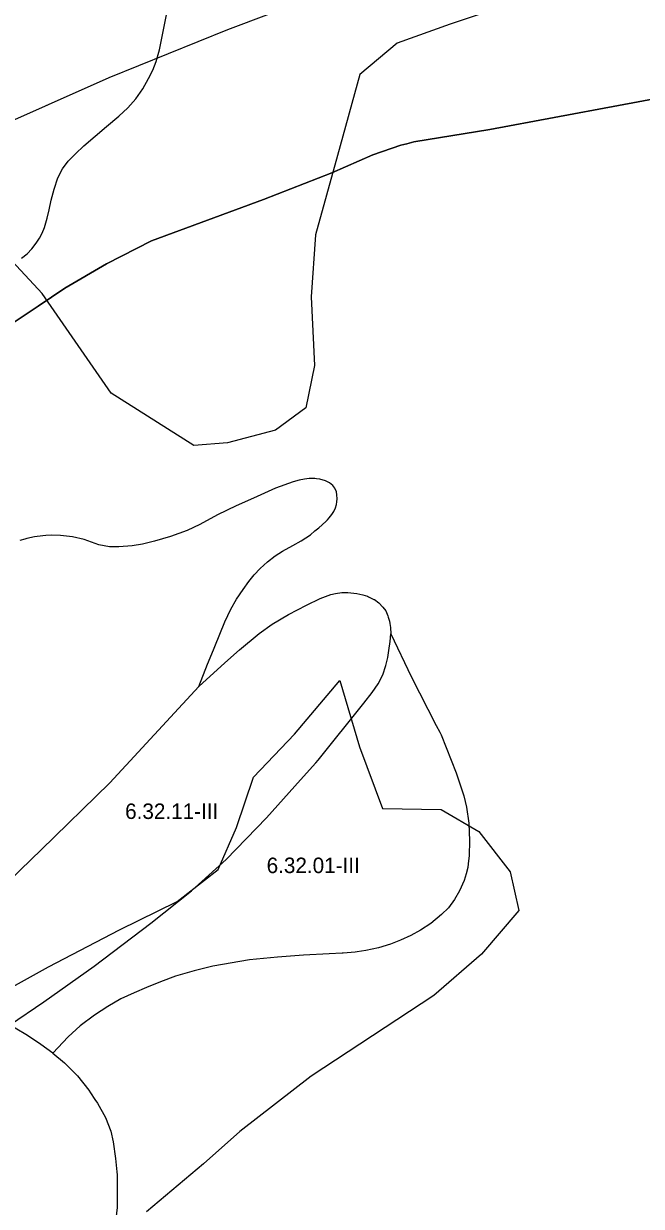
# Model space of a CAD drawing. Extents: x -555156 to -540209, y -1046851 to -1035695.
# Drawn here: x -542146 to -541747, y -1038196 to -1037432 of the extents above; entities that cross this region are included whole.
import ezdxf

# ---------------------------------------------------------------- set-up
doc = ezdxf.new("R2010")
doc.units = 0
for name, color, linetype in [('Vrstva 27', 7, 'Continuous'), ('Vrstva 28', 7, 'Continuous'), ('Vrstva 29', 7, 'Continuous')]:
    doc.layers.add(name, color=color, linetype=linetype)

msp = doc.modelspace()

# ---------------------------------------------------------------- linework, layer by layer
at = {"layer": 'Vrstva 28'}
for points in [[(-542147.76, -1037583.51), (-542144.18, -1037580.64), (-542141.08, -1037577.62), (-542138.22, -1037573.88), (-542136.15, -1037570.69), (-542134.32, -1037567.43), (-542132.8, -1037563.69), (-542131.05, -1037557.64), (-542129.78, -1037552.25), (-542128.66, -1037545.98), (-542126.57, -1037539.01), (-542124.21, -1037531.63), (-542121.14, -1037525.78), (-542117.52, -1037520.76), (-542112.93, -1037516.16), (-542107.36, -1037511.01), (-542092.86, -1037498.54), (-542084.78, -1037491.71), (-542078.93, -1037486.42), (-542073.78, -1037480.57), (-542069.32, -1037474.16), (-542065.7, -1037467.47), (-542062.92, -1037462.04), (-542060.69, -1037456.47), (-542058.53, -1037448.91), (-542049.27, -1037402.1)], [(-541720.19, -1037477.06), (-541844.94, -1037500.38), (-541894.08, -1037508.4), (-541898.72, -1037509.58), (-541902.61, -1037510.57), (-541920.68, -1037516.81), (-541947.21, -1037528.47), (-541991.27, -1037545.59), (-542063.6, -1037572.3), (-542092.72, -1037587.26), (-542119.74, -1037602.87), (-542137.04, -1037614.48), (-542160.81, -1037630.43), (-542163.69, -1037632.79), (-542194.71, -1037658.28), (-542217.42, -1037678.3), (-542231.55, -1037691.99)], [(-542229.29, -1037689.8), (-542217.42, -1037678.3), (-542194.71, -1037658.28), (-542163.69, -1037632.79), (-542160.81, -1037630.43), (-542137.04, -1037614.48), (-542119.74, -1037602.87), (-542092.72, -1037587.26), (-542063.6, -1037572.3), (-541991.27, -1037545.59), (-541947.21, -1037528.47), (-541920.68, -1037516.81), (-541902.61, -1037510.57), (-541898.72, -1037509.58), (-541894.08, -1037508.4), (-541844.94, -1037500.38), (-541720.19, -1037477.06)], [(-541972.41, -1037769.17), (-541966.87, -1037766.27), (-541960.98, -1037762.25), (-541958.08, -1037759.82), (-541955.6, -1037757.73), (-541951.09, -1037753.61), (-541950.04, -1037752.6), (-541948.8, -1037751.41), (-541947.04, -1037749.12), (-541945.77, -1037747.21), (-541944.75, -1037744.92), (-541944.17, -1037742.82), (-541943.87, -1037740.92), (-541943.73, -1037739.06), (-541943.82, -1037736.48), (-541944.17, -1037734.53), (-541945.29, -1037732.09), (-541946.46, -1037730.43), (-541948.65, -1037728.67), (-541951.29, -1037727.35), (-541954.99, -1037726.38), (-541956.94, -1037726.16), (-541958.07, -1037726.03), (-541961.77, -1037726.03), (-541964.85, -1037726.33), (-541968.16, -1037726.91), (-541972.17, -1037728.08), (-541983.52, -1037732.12), (-541997.86, -1037738.54), (-542008.91, -1037743.62), (-542021.01, -1037749.45), (-542032.36, -1037755.58), (-542040.73, -1037759.46), (-542051.48, -1037763.35), (-542061.79, -1037766.49), (-542069.56, -1037768.28), (-542076.13, -1037769.33), (-542084.79, -1037770.08), (-542090.92, -1037770.08), (-542097.64, -1037768.73), (-542107.17, -1037765.31), (-542114.76, -1037763.6), (-542122.45, -1037762.66), (-542128.25, -1037762.58), (-542131.97, -1037762.86), (-542134.05, -1037763.01), (-542139.26, -1037763.69), (-542144.38, -1037764.71), (-542145.51, -1037765.06), (-542148.82, -1037766.08)], [(-542033.02, -1037860.31), (-542027.49, -1037845.96), (-542023.61, -1037836.55), (-542022.74, -1037834.42), (-542016.29, -1037818.62), (-542012.41, -1037810.4), (-542008.67, -1037803.82), (-542004.51, -1037797.61), (-542000.75, -1037792.48), (-541997.34, -1037788.21), (-541993.41, -1037784.03), (-541988.63, -1037779.76), (-541983.85, -1037775.92), (-541978.99, -1037772.93), (-541972.41, -1037769.17)], [(-542033.02, -1037860.31), (-542016.27, -1037845.08), (-542006.71, -1037836.56), (-541994.02, -1037826.1), (-541985.65, -1037820.12), (-541975.2, -1037813.84), (-541963.55, -1037807.71), (-541954.73, -1037803.38), (-541947.86, -1037800.84), (-541944.66, -1037800.18), (-541940.65, -1037799.67), (-541936.89, -1037799.67), (-541931, -1037800.18), (-541927.16, -1037801.03), (-541924.01, -1037802.06), (-541923.4, -1037802.35), (-541919.91, -1037804.02), (-541919.65, -1037804.2), (-541916.67, -1037806.33), (-541914.1, -1037809.06), (-541912.31, -1037811.54), (-541910.95, -1037814.61), (-541910.65, -1037815.56), (-541909.84, -1037818.11), (-541909.61, -1037819.66), (-541909.24, -1037822.13), (-541909.07, -1037826.31)], [(-541909.07, -1037826.31), (-541895.83, -1037853.87), (-541879.6, -1037885.47), (-541877.39, -1037889.78), (-541876.49, -1037891.53), (-541866.82, -1037916.11), (-541861.81, -1037931.05), (-541860.02, -1037938.22), (-541858.53, -1037948.68), (-541858.08, -1037960.04), (-541858.38, -1037969.61), (-541858.9, -1037974.99), (-541859.12, -1037977.23), (-541860.32, -1037981.45), (-541861.51, -1037985.6), (-541864.5, -1037992.32), (-541867.79, -1037998), (-541871.82, -1038003.38), (-541876.15, -1038007.72), (-541883.17, -1038013.55), (-541889.89, -1038017.88), (-541896.17, -1038021.32), (-541902.74, -1038024.31), (-541909.16, -1038026.85), (-541916.93, -1038029.24), (-541925.14, -1038031.03), (-541930.85, -1038031.9), (-541932.01, -1038032.08), (-541939.75, -1038032.62), (-541940.53, -1038032.68), (-541948.82, -1038032.98), (-541965.55, -1038034.03), (-541982.28, -1038035.34), (-542000.31, -1038036.91), (-542024.1, -1038041.09), (-542036.12, -1038044.15), (-542048.21, -1038047.58), (-542057.92, -1038051.17), (-542066.89, -1038054.76), (-542074.8, -1038058.34), (-542083.47, -1038062.23), (-542091.83, -1038067.16), (-542100.49, -1038072.69), (-542109.9, -1038079.57), (-542117.67, -1038086.74)], [(-542100.81, -1038041), (-542064.21, -1038013.28), (-542037.81, -1037992.36), (-542015.33, -1037972.22), (-541989.26, -1037945.15), (-541967.29, -1037920.64), (-541957.37, -1037909.58), (-541956.03, -1037907.91), (-541926.48, -1037871.04), (-541921.1, -1037864.29), (-541917.18, -1037858.66), (-541914.19, -1037852.76), (-541912.14, -1037846.78), (-541910.95, -1037841.49), (-541910.18, -1037837.13), (-541909.32, -1037831.18), (-541909.07, -1037826.31)], [(-542235.22, -1038063.08), (-542227.34, -1038056.08), (-542194.7, -1038027.09), (-542156.8, -1037987.08), (-542141.27, -1037971.92), (-542135.22, -1037966.01), (-542090.66, -1037922.48), (-542033.02, -1037860.31)], [(-542155.48, -1038079.25), (-542133.22, -1038064.02), (-542100.81, -1038041)], [(-542127.56, -1038097.28), (-542135.33, -1038091.6), (-542143.84, -1038085.92), (-542151.76, -1038081.14), (-542155.48, -1038079.25)], [(-542117.67, -1038086.74), (-542127.56, -1038097.28)], [(-542127.56, -1038097.28), (-542119.95, -1038103.56), (-542111.58, -1038111.93), (-542104.26, -1038121.19), (-542103.03, -1038123.01), (-542100.24, -1038127.12), (-542098.59, -1038129.56), (-542093.51, -1038138.83), (-542090.07, -1038147.65), (-542088.53, -1038154.67), (-542086.89, -1038165.28), (-542086.03, -1038173.99), (-542085.84, -1038175.89), (-542085.84, -1038188.6)], [(-542085.84, -1038188.6), (-542085.99, -1038196.97), (-542087.04, -1038206.23), (-542088.98, -1038214.6), (-542093.01, -1038224.17), (-542097.34, -1038231.19), (-542103.02, -1038238.36), (-542107.95, -1038243.44), (-542114.37, -1038248.97), (-542121.24, -1038254.2), (-542129.46, -1038259.88), (-542142.15, -1038267.53)]]:
    msp.add_lwpolyline(points, dxfattribs=at)
at = {"layer": 'Vrstva 29'}
for points in [[(-541821.079003, -1037415.468001), (-541870.693001, -1037432.305008), (-541904.918995, -1037444.584995), (-541929.102006, -1037464.965997), (-541943.507008, -1037517.192009), (-541957.790997, -1037568.410005), (-541960.511001, -1037608.478995), (-541958.379999, -1037652.962001), (-541963.920004, -1037680.168008), (-541983.566991, -1037694.698001), (-542014.476998, -1037702.771996), (-542036.440006, -1037704.500009), (-542089.766994, -1037670.784994), (-542134.328004, -1037606.414007), (-542173.612991, -1037564.402994), (-542211.293998, -1037521.816995), (-542171.624994, -1037502.516008), (-542091.103991, -1037466.867001), (-542014.463, -1037435.867993), (-541935.387997, -1037405.927008)], [(-542304.833994, -1038204.771001), (-542263.651006, -1038159.828994), (-542219.387001, -1038108.352009), (-542180.971998, -1038069.471006), (-542130.291007, -1038041.511995), (-542084.438992, -1038017.579998), (-542047.191992, -1037999.267999), (-542020.678005, -1037978.653997), (-542008.737996, -1037951.443994), (-541997.711991, -1037919.012008), (-541971.367993, -1037891.219008), (-541941.881994, -1037856.386993), (-541929.325004, -1037899.300996), (-541914.359991, -1037939.178006), (-541876.556001, -1037939.851993), (-541852.131002, -1037954.012999), (-541831.952995, -1037980.195997), (-541826.219997, -1038005.167008), (-541850.292991, -1038033.229994), (-541881.120997, -1038059.977), (-541960.532993, -1038112.120992), (-542006.502005, -1038147.800003), (-542029.986992, -1038168.774999), (-542066.966991, -1038199.901006)]]:
    msp.add_lwpolyline(points, dxfattribs=at)

# ---------------------------------------------------------------- texts
at = {"layer": 'Vrstva 27'}
for s, p in [('6.32.11-III', (-542080.746548, -1037945.94)), ('6.32.01-III', (-541989.266548, -1037980.91))]:
    msp.add_text(s, height=10, dxfattribs=at).set_placement(p)

doc.saveas('drawing.dxf')
